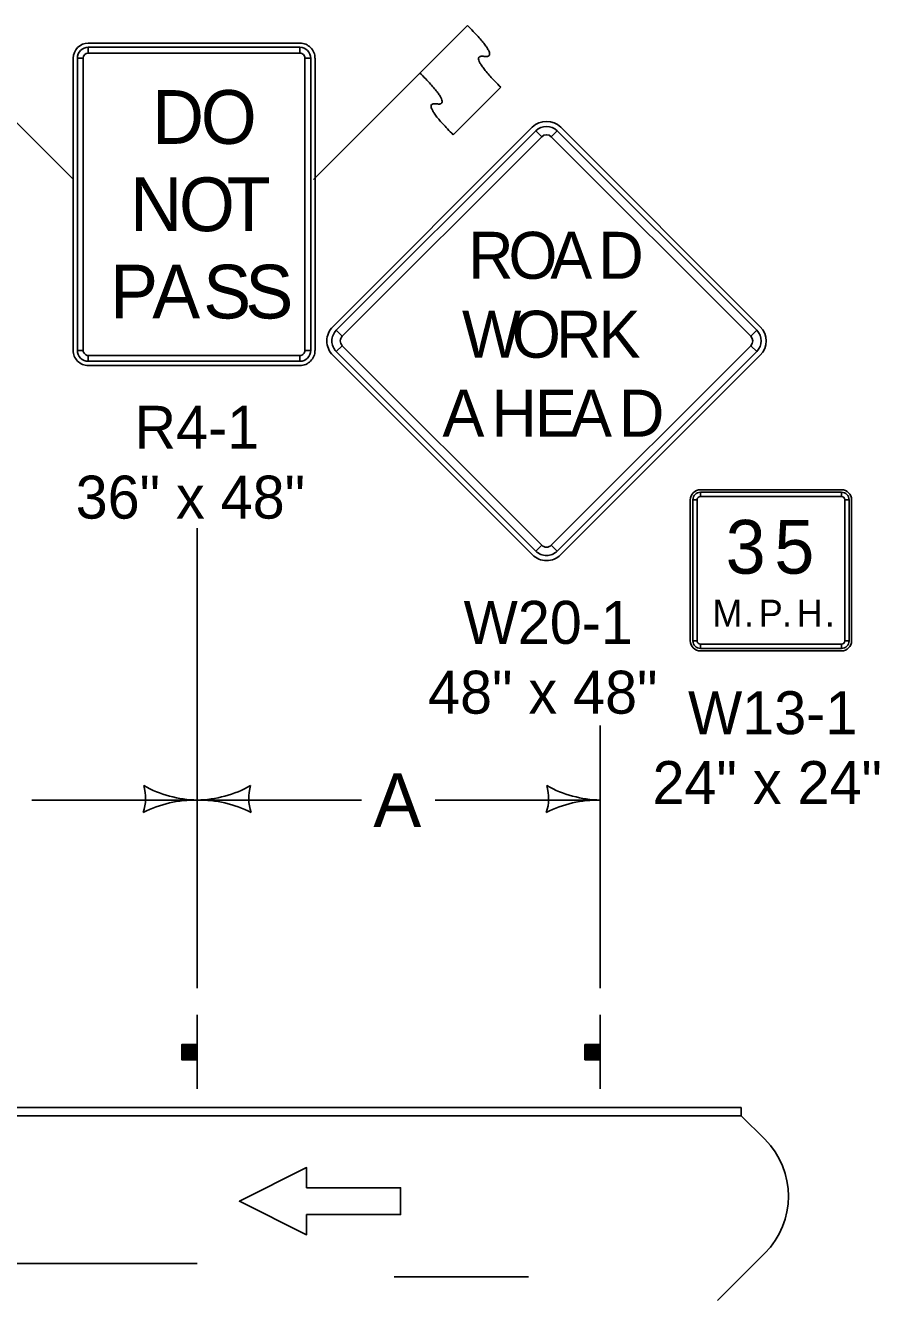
# Model space of a CAD drawing. Extents: x 10133 to 81668, y 4692 to 11018.
# Drawn here: x 23738.6 to 24056.4, y 6856 to 7330.6 of the extents above; entities that cross this region are included whole.
import ezdxf

# ---------------------------------------------------------------- set-up
doc = ezdxf.new("R2010")
doc.units = 0
for name, color, linetype in [('dsnCellElements', 7, 'Continuous'), ('dsnTextTabulation', 7, 'Continuous'), ('Level 5', 7, 'Continuous'), ('SheetAddendum', 7, 'Continuous')]:
    doc.layers.add(name, color=color, linetype=linetype)

msp = doc.modelspace()

# ---------------------------------------------------------------- linework, layer by layer
at = {"layer": 'dsnCellElements'}
for p, q in [((23802.53, 6972.3), (23802.53, 7143.54)), ((23952.53, 6972.3), (23952.53, 7069.99)), ((23741.03, 7042.3), (23802.53, 7042.3)), ((23802.53, 7042.3), (23863.7, 7042.3)), ((23891.03, 7042.3), (23952.53, 7042.3)), ((23802.53, 6934.8), (23802.53, 6962.3)), ((23952.53, 6934.8), (23952.53, 6962.3)), ((23797.2, 6945.67), (23797.2, 6951.25)), ((23797.52, 6951.25), (23797.52, 6945.67)), ((23797.75, 6945.67), (23797.75, 6951.25)), ((23798.06, 6951.25), (23798.06, 6945.67)), ((23798.29, 6945.67), (23798.27, 6951.25)), ((23798.7, 6951.25), (23798.72, 6945.67)), ((23798.93, 6945.67), (23798.93, 6951.25)), ((23799.36, 6951.25), (23799.36, 6945.67)), ((23799.73, 6945.67), (23799.73, 6951.25)), ((23800.05, 6951.25), (23800.07, 6945.67)), ((23800.28, 6945.67), (23800.28, 6951.25)), ((23800.54, 6951.25), (23800.54, 6945.67)), ((23800.88, 6945.67), (23800.88, 6951.25)), ((23801.08, 6951.25), (23801.08, 6945.67)), ((23801.31, 6945.67), (23801.31, 6951.25)), ((23801.57, 6951.25), (23801.57, 6945.67)), ((23801.83, 6945.67), (23801.83, 6951.25)), ((23802.11, 6951.25), (23802.11, 6945.67)), ((23947.2, 6945.67), (23947.2, 6951.25)), ((23947.52, 6951.25), (23947.52, 6945.67)), ((23947.75, 6945.67), (23947.75, 6951.25)), ((23948.06, 6951.25), (23948.06, 6945.67)), ((23948.29, 6945.67), (23948.27, 6951.25)), ((23948.7, 6951.25), (23948.72, 6945.67)), ((23948.93, 6945.67), (23948.93, 6951.25)), ((23949.36, 6951.25), (23949.36, 6945.67)), ((23949.73, 6945.67), (23949.73, 6951.25)), ((23950.05, 6951.25), (23950.07, 6945.67)), ((23950.28, 6945.67), (23950.28, 6951.25)), ((23950.54, 6951.25), (23950.54, 6945.67)), ((23950.88, 6945.67), (23950.88, 6951.25)), ((23951.08, 6951.25), (23951.08, 6945.67)), ((23951.31, 6945.67), (23951.31, 6951.25)), ((23951.57, 6951.25), (23951.57, 6945.67)), ((23951.83, 6945.67), (23951.83, 6951.25)), ((23952.11, 6951.25), (23952.11, 6945.67)), ((24004.98, 6924.8), (22692.53, 6924.8)), ((24004.98, 6927.8), (24004.98, 6924.8)), ((24013.77, 6916.02), (24004.98, 6924.8)), ((24013.77, 6916.02), (24004.98, 6924.8)), ((23996.2, 6856.02), (24013.77, 6873.59)), ((23996.2, 6856.02), (24013.77, 6873.59))]:
    msp.add_line(p, q, dxfattribs=at)
for points in [[(23802.43, 6951.25), (23802.43, 6945.63), (23796.81, 6945.63), (23796.81, 6951.25)], [(23952.43, 6951.25), (23952.43, 6945.63), (23946.81, 6945.63), (23946.81, 6951.25)], [(23878.23, 6887.97), (23878.23, 6897.97), (23843.23, 6897.97), (23843.23, 6905.47), (23818.23, 6892.97), (23843.23, 6880.47), (23843.23, 6887.97)]]:
    msp.add_lwpolyline(points, close=True, dxfattribs=at)
msp.add_lwpolyline([(23843.23, 6887.97), (23843.23, 6880.47), (23818.23, 6892.97), (23843.23, 6905.47), (23843.23, 6897.97), (23878.23, 6897.97), (23878.23, 6887.97), (23843.23, 6887.97)], dxfattribs=at)
for centre, radius, start, end in [((23766.91, 7042.93), 16.42, 341.2666, 16.7334), ((23803.28, 7084.8), 42.5, 240.9275, 268.9824), ((23801.77, 7084.8), 42.5, 271.0176, 299.0725), ((23838.14, 7042.93), 16.42, 163.2666, 198.7334), ((23916.91, 7042.93), 16.42, 341.2666, 16.7334), ((23953.28, 7084.8), 42.5, 240.9275, 268.9824), ((23801.8, 6999.81), 42.5, 89.0176, 117.0725), ((23803.26, 6999.81), 42.5, 62.9275, 90.9824), ((23951.8, 6999.81), 42.5, 89.0176, 117.0725), ((23992.56, 6894.8), 30, 315, 45), ((23992.56, 6894.8), 30, 315, 45)]:
    msp.add_arc(centre, radius, start, end, dxfattribs=at)
at = {"layer": 'dsnTextTabulation'}
for p, q in [((24004.98, 6927.8), (23319.96, 6927.8)), ((23357.53, 6924.8), (24004.98, 6924.8)), ((24004.98, 6924.8), (24004.98, 6927.8)), ((23352.53, 6869.8), (23802.53, 6869.8)), ((23875.82, 6864.8), (23875.82, 6864.8)), ((23875.82, 6864.8), (23925.82, 6864.8))]:
    msp.add_line(p, q, dxfattribs=at)
for points in [[(22692.53, 6927.8), (24004.98, 6927.8)], [(22692.53, 6924.8), (24004.98, 6924.8)]]:
    msp.add_lwpolyline(points, dxfattribs=at)
at = {"layer": 'Level 5'}
msp.add_line((23915.5, 7307.61), (23897.82, 7289.93), dxfattribs=at)
for points in [[(23903.12, 7330.6), (23915.5, 7318.22), (23903.12, 7319.99), (23915.5, 7307.61)], [(23885.44, 7312.92), (23897.82, 7300.54), (23885.45, 7302.31), (23897.82, 7289.93)]]:
    msp.add_open_spline(points, degree=2, dxfattribs=at)
at = {"layer": 'SheetAddendum'}
for p, q in [((23756.51, 7273.29), (23699.17, 7330.59)), ((23845.8, 7273.29), (23903.12, 7330.6)), ((23903.12, 7330.6), (23885.44, 7312.92)), ((23840.75, 7324.05), (23762, 7324.05)), ((23756.38, 7318.42), (23756.38, 7209.67)), ((23757.94, 7318.42), (23760.13, 7318.42)), ((23762, 7320.3), (23762, 7322.48)), ((23840.75, 7322.48), (23840.75, 7320.3)), ((23842.63, 7318.42), (23844.81, 7318.42)), ((23846.38, 7209.67), (23846.38, 7318.42)), ((23897.82, 7289.93), (23915.5, 7307.61)), ((23927.22, 7292.74), (23852.98, 7218.49)), ((23928.55, 7291.41), (23930.76, 7289.2)), ((23934.29, 7289.2), (23936.5, 7291.41)), ((24012.08, 7218.49), (23937.83, 7292.74)), ((23856.51, 7214.96), (23854.3, 7217.16)), ((24010.75, 7217.16), (24008.54, 7214.96)), ((23760.13, 7209.67), (23757.94, 7209.67)), ((23844.81, 7209.67), (23842.63, 7209.67)), ((23854.3, 7209.21), (23856.51, 7211.42)), ((24008.54, 7211.42), (24010.75, 7209.21)), ((23762, 7205.61), (23762, 7207.8)), ((23840.75, 7207.8), (23840.75, 7205.61)), ((23852.98, 7207.88), (23927.22, 7133.64)), ((23937.83, 7133.64), (24012.08, 7207.88)), ((23762, 7204.05), (23840.75, 7204.05)), ((24042.3, 7157.8), (23989.8, 7157.8)), ((23989.8, 7155.3), (23989.8, 7156.86)), ((24042.3, 7156.86), (24042.3, 7155.3)), ((23986.05, 7154.05), (23986.05, 7101.55)), ((23986.99, 7154.05), (23988.55, 7154.05)), ((24043.55, 7154.05), (24045.11, 7154.05)), ((24046.05, 7101.55), (24046.05, 7154.05)), ((23930.76, 7137.17), (23928.55, 7134.96)), ((23936.5, 7134.96), (23934.29, 7137.17)), ((23988.55, 7101.55), (23986.99, 7101.55)), ((23989.8, 7098.73), (23989.8, 7100.3)), ((24042.3, 7100.3), (24042.3, 7098.73)), ((24045.11, 7101.55), (24043.55, 7101.55)), ((23989.8, 7097.8), (24042.3, 7097.8))]:
    msp.add_line(p, q, dxfattribs=at)
for points in [[(23757.94, 7318.42), (23757.94, 7209.67), (23760.13, 7209.67), (23760.13, 7318.42), (23757.94, 7318.42)], [(23840.75, 7322.48), (23762, 7322.48), (23762, 7320.3), (23840.75, 7320.3), (23840.75, 7322.48)], [(23844.81, 7209.67), (23844.81, 7318.42), (23842.63, 7318.42), (23842.63, 7209.67), (23844.81, 7209.67)], [(23928.55, 7291.41), (23854.3, 7217.16), (23856.51, 7214.96), (23930.76, 7289.2), (23928.55, 7291.41)], [(24010.75, 7217.16), (23936.5, 7291.41), (23934.29, 7289.2), (24008.54, 7214.96), (24010.75, 7217.16)], [(23854.3, 7209.21), (23928.55, 7134.96), (23930.76, 7137.17), (23856.51, 7211.42), (23854.3, 7209.21)], [(23936.5, 7134.96), (24010.75, 7209.21), (24008.54, 7211.42), (23934.29, 7137.17), (23936.5, 7134.96)], [(23762, 7205.61), (23840.75, 7205.61), (23840.75, 7207.8), (23762, 7207.8), (23762, 7205.61)], [(24042.3, 7156.86), (23989.8, 7156.86), (23989.8, 7155.3), (24042.3, 7155.3), (24042.3, 7156.86)], [(23986.99, 7154.05), (23986.99, 7101.55), (23988.55, 7101.55), (23988.55, 7154.05), (23986.99, 7154.05)], [(24045.11, 7101.55), (24045.11, 7154.05), (24043.55, 7154.05), (24043.55, 7101.55), (24045.11, 7101.55)], [(23989.8, 7098.73), (24042.3, 7098.73), (24042.3, 7100.3), (23989.8, 7100.3), (23989.8, 7098.73)]]:
    msp.add_lwpolyline(points, close=True, dxfattribs=at)
for centre, radius, start, end in [((23762, 7318.42), 5.62, 90.0002, 179.9998), ((23840.75, 7318.42), 5.62, 0, 90.0002), ((23762, 7318.42), 4.06, 90.0002, 179.9998), ((23762, 7318.42), 1.88, 90.0002, 179.9998), ((23840.75, 7318.42), 4.06, 0, 90.0002), ((23840.75, 7318.42), 1.88, 0, 90.0002), ((23932.53, 7287.43), 7.5, 45, 134.9997), ((23932.53, 7287.43), 5.62, 45, 134.9997), ((23932.53, 7287.43), 2.5, 45, 134.9997), ((23858.28, 7213.19), 7.5, 134.9997, 225), ((24006.77, 7213.19), 7.5, 315.0002, 44.9998), ((23858.28, 7213.19), 5.62, 134.9997, 225), ((23858.28, 7213.19), 2.5, 134.9997, 225), ((24006.77, 7213.19), 2.5, 315.0002, 44.9998), ((24006.77, 7213.19), 5.62, 315.0002, 44.9998), ((23762, 7209.67), 5.62, 179.9998, 270.0001), ((23762, 7209.67), 4.06, 179.9998, 270.0001), ((23762, 7209.67), 1.88, 179.9998, 270.0001), ((23840.75, 7209.67), 5.62, 270.0001, 0.0003), ((23840.75, 7209.67), 4.06, 270.0001, 0.0003), ((23840.75, 7209.67), 1.88, 270.0001, 0.0003), ((23989.8, 7154.05), 3.75, 90.0002, 179.9998), ((23989.8, 7154.05), 2.81, 90.0002, 179.9998), ((24042.3, 7154.05), 3.75, 0, 90.0002), ((24042.3, 7154.05), 2.81, 0, 90.0002), ((23989.8, 7154.05), 1.25, 90.0002, 179.9998), ((24042.3, 7154.05), 1.25, 0, 90.0002), ((23932.53, 7138.94), 7.5, 225, 315.0002), ((23932.53, 7138.94), 5.62, 225, 315.0002), ((23932.53, 7138.94), 2.5, 225, 315.0002), ((23989.8, 7101.55), 3.75, 179.9998, 270.0001), ((23989.8, 7101.55), 2.81, 179.9998, 270.0001), ((23989.8, 7101.55), 1.25, 179.9998, 270.0001), ((24042.3, 7101.55), 3.75, 270.0001, 0.0003), ((24042.3, 7101.55), 2.81, 270.0001, 0.0003), ((24042.3, 7101.55), 1.25, 270.0001, 0.0003)]:
    msp.add_arc(centre, radius, start, end, dxfattribs=at)
for points in [[(23915.5, 7307.61), (23903.12, 7319.99), (23915.5, 7318.22), (23903.12, 7330.6)], [(23885.44, 7312.92), (23897.82, 7300.54), (23885.45, 7302.31), (23897.82, 7289.93)]]:
    msp.add_open_spline(points, degree=2, dxfattribs=at)

# ---------------------------------------------------------------- texts
at = {"layer": 'dsnCellElements'}
msp.add_text('A', height=20, dxfattribs=at).set_placement((23868.08, 7032.23))
at = {"layer": 'SheetAddendum'}
for s, height, p in [('D', 20, (23785.75, 7286.55)), ('O', 20, (23803.88, 7286.55)), ('N', 20, (23777.62, 7254.05)), ('O', 20, (23795.75, 7254.05)), ('T', 20, (23813.56, 7254.05)), ('R', 17.5, (23903.37, 7236.31)), ('O', 17.5, (23918.37, 7236.31)), ('A', 17.5, (23933.93, 7236.31)), ('D', 17.5, (23951.8, 7236.31)), ('P', 20, (23770.11, 7221.55)), ('A', 20, (23785.8, 7221.55)), ('S', 20, (23804.77, 7221.55)), ('S', 20, (23820.45, 7221.55)), ('W', 17.5, (23901.08, 7206.94)), ('O', 17.5, (23919.67, 7206.94)), ('R', 17.5, (23936.08, 7206.94)), ('K', 17.5, (23951.94, 7206.94)), ('A', 17.5, (23893.8, 7177.56)), ('H', 17.5, (23912.01, 7177.56)), ('E', 17.5, (23928.24, 7177.56)), ('A', 17.5, (23941.29, 7177.56)), ('D', 17.5, (23959.49, 7177.56)), ('R4-1', 16, (23779.21, 7173.05)), ('36" x 48"', 16, (23757.31, 7147.05)), ('3', 20, (23999.2, 7126.56)), ('5', 20, (24017.32, 7126.56)), ('W20-1', 16, (23901.67, 7100.44)), ('M', 10, (23994.27, 7106.86)), ('P', 10, (24011.53, 7106.86)), ('H', 10, (24025.65, 7106.86)), ('.', 10, (24006.07, 7106.86)), ('.', 10, (24020.19, 7106.86)), ('.', 10, (24036.11, 7106.86)), ('48" x 48"', 16, (23888.46, 7074.44)), ('W13-1', 16, (23985.19, 7066.8)), ('24" x 24"', 16, (23971.98, 7040.8))]:
    msp.add_text(s, height=height, dxfattribs=at).set_placement(p)

doc.saveas('drawing.dxf')
